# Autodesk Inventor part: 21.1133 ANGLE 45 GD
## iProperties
Created: 2007-01
Part Number: 21.1133 ANGLE 45 GD
Document SubType Name: Modeling
Designer: Andy Moles
Material: Aluminum-6061
Mass: 78.4439 g
Surface Area: 105.352 cm^2
Volume: 28.9461 cm^3
Density: 2.71 g/cm^3
Author: Andy Moles
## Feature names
1. Extrusion1
2. Extrusion2
3. Extrusion3
4. Extrusion4
